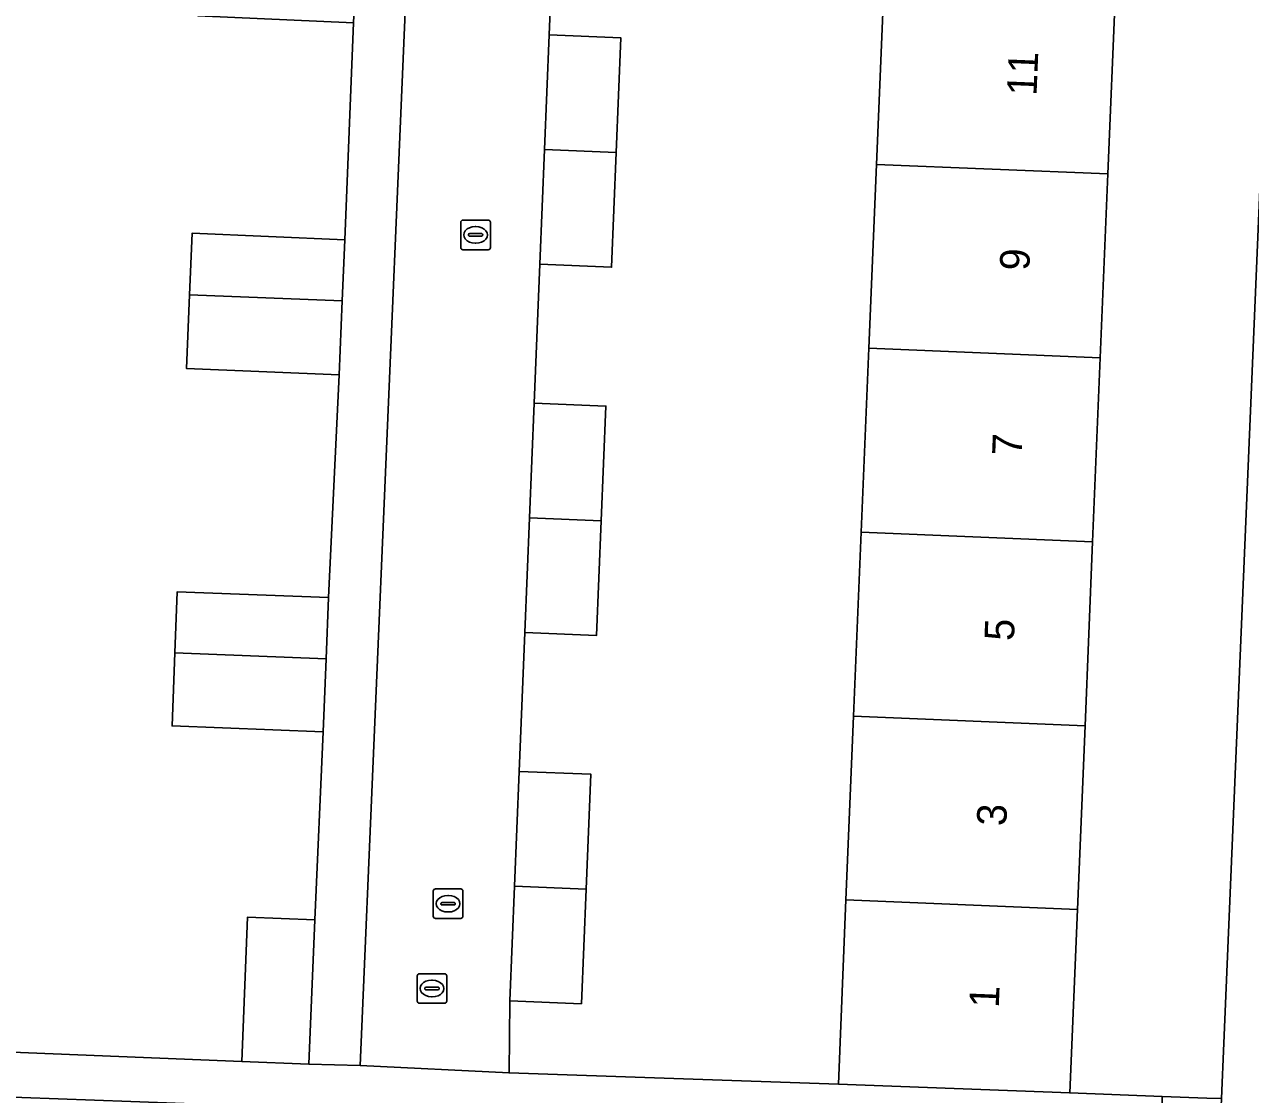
# Model space of a CAD drawing. Extents: x 161354 to 162026, y 386504 to 387460.
# Drawn here: x 161513.06 to 161554.51, y 386686.96 to 386723.13 of the extents above; entities that cross this region are included whole.
import ezdxf

# ---------------------------------------------------------------- set-up
doc = ezdxf.new("R2010")
doc.units = 0
for name, color, linetype in [('IMGEO_Erf', 7, 'Continuous'), ('IMGEO_Kolk', 7, 'Continuous'), ('IMGEO_Pand', 7, 'Continuous'), ('IMGEO_Pand_nummerreeks', 7, 'Continuous'), ('IMGEO_Rijbaan_lokaal_open', 7, 'Continuous'), ('IMGEO_Rioolput', 7, 'Continuous'), ('IMGEO_Voetpad_open', 7, 'Continuous')]:
    doc.layers.add(name, color=color, linetype=linetype)

msp = doc.modelspace()

# ---------------------------------------------------------------- linework, layer by layer
at = {"layer": 'IMGEO_Erf'}
for points in [[(161549.945, 386724.294), (161549.688, 386718.078), (161549.43, 386711.861), (161549.173, 386705.644), (161548.916, 386699.427), (161548.658, 386693.211), (161548.402, 386687.013), (161551.52, 386686.895), (161553.035, 386686.838), (161553.534, 386686.819), (161556.007, 386745.625)], [(161496.538, 386689.04), (161520.399, 386688.074), (161520.597, 386692.953), (161522.87, 386692.861), (161523.157, 386699.22), (161518.043, 386699.418), (161518.138, 386701.89), (161518.218, 386703.953), (161523.332, 386703.755), (161523.69, 386711.288), (161518.532, 386711.505), (161518.637, 386713.996), (161518.724, 386716.073), (161523.882, 386715.856), (161524.182, 386723.194), (161518.919, 386723.421), (161519.035, 386726.105), (161519.121, 386728.084), (161524.383, 386727.857), (161524.785, 386736.896), (161522.407, 386736.993), (161522.622, 386742.251), (161521.337, 386742.294), (161500, 386743.01)], [(161530.986, 386727.476), (161530.794, 386722.78), (161533.222, 386722.68), (161533.064, 386718.803), (161532.906, 386714.926), (161530.478, 386715.026), (161530.286, 386710.332), (161532.714, 386710.231), (161532.556, 386706.354), (161532.398, 386702.477), (161529.97, 386702.578), (161529.778, 386697.882), (161532.206, 386697.782), (161532.048, 386693.905), (161531.889, 386690.028), (161529.461, 386690.128), (161529.439, 386687.685), (161540.576, 386687.31), (161540.833, 386693.535), (161541.091, 386699.751), (161541.348, 386705.968), (161541.605, 386712.185), (161541.863, 386718.402), (161542.12, 386724.618)]]:
    msp.add_lwpolyline(points, dxfattribs=at)
at = {"layer": 'IMGEO_Kolk'}
for p, q in [((161527.807, 386715.593), (161527.807, 386716.445)), ((161527.882, 386716.519), (161528.734, 386716.519)), ((161528.295, 386716.299), (161528.32, 386716.299)), ((161528.808, 386716.445), (161528.808, 386715.593)), ((161528.066, 386716.013), (161528.066, 386716.025)), ((161528.504, 386715.976), (161528.106, 386715.976)), ((161528.109, 386716.062), (161528.507, 386716.062)), ((161528.318, 386715.739), (161528.293, 386715.739)), ((161528.55, 386716.025), (161528.55, 386716.013)), ((161528.734, 386715.519), (161527.882, 386715.519)), ((161526.879, 386692.982), (161526.879, 386693.834)), ((161526.954, 386693.908), (161527.806, 386693.908)), ((161527.88, 386693.834), (161527.88, 386692.982)), ((161527.138, 386693.402), (161527.138, 386693.414)), ((161527.576, 386693.365), (161527.178, 386693.365)), ((161527.181, 386693.451), (161527.579, 386693.451)), ((161527.367, 386693.688), (161527.392, 386693.688)), ((161527.622, 386693.414), (161527.622, 386693.402)), ((161527.806, 386692.908), (161526.954, 386692.908)), ((161527.39, 386693.128), (161527.365, 386693.128))]:
    msp.add_line(p, q, dxfattribs=at)
for points in [[(161527.807, 386715.593), (161527.807, 386716.445)], [(161527.882, 386716.519), (161528.734, 386716.519)], [(161528.808, 386716.445), (161528.808, 386715.593)], [(161528.734, 386715.519), (161527.882, 386715.519)], [(161526.879, 386692.982), (161526.879, 386693.834)], [(161526.954, 386693.908), (161527.806, 386693.908)], [(161527.88, 386693.834), (161527.88, 386692.982)], [(161527.806, 386692.908), (161526.954, 386692.908)]]:
    msp.add_lwpolyline(points, dxfattribs=at)
for centre, radius, start, end in [((161527.884, 386716.443), 0.0765, 91.552, 178.448), ((161527.884, 386716.443), 0.0765, 91.552, 178.448), ((161528.732, 386716.443), 0.0765, 1.552, 88.448), ((161528.732, 386716.443), 0.0765, 1.552, 88.448), ((161528.106, 386716.022), 0.0403, 85.8775, 175.7526), ((161528.103, 386716.012), 0.0366, 178.938, 274.7102), ((161528.507, 386716.019), 0.043, 264.8664, 352.4533), ((161528.511, 386716.024), 0.0386, 1.7309, 96.639), ((161527.884, 386715.595), 0.0765, 181.552, 268.448), ((161527.884, 386715.595), 0.0765, 181.552, 268.448), ((161528.732, 386715.595), 0.0765, 271.552, 358.448), ((161528.732, 386715.595), 0.0765, 271.552, 358.448), ((161526.956, 386693.832), 0.0765, 91.552, 178.448), ((161526.956, 386693.832), 0.0765, 91.552, 178.448), ((161527.804, 386693.832), 0.0765, 1.552, 88.448), ((161527.804, 386693.832), 0.0765, 1.552, 88.448), ((161527.178, 386693.411), 0.0403, 85.8775, 175.7526), ((161527.175, 386693.401), 0.0366, 178.938, 274.7102), ((161527.579, 386693.408), 0.043, 264.8664, 352.4533), ((161527.583, 386693.413), 0.0386, 1.7309, 96.639), ((161526.956, 386692.984), 0.0765, 181.552, 268.448), ((161526.956, 386692.984), 0.0765, 181.552, 268.448), ((161527.804, 386692.984), 0.0765, 271.552, 358.448), ((161527.804, 386692.984), 0.0765, 271.552, 358.448)]:
    msp.add_arc(centre, radius, start, end, dxfattribs=at)
for centre, major_axis, ratio, start_param, end_param in [((161528.294, 386716.019), (-0.387, 0.002), 0.722429, 4.712389, 7.853982), ((161528.319, 386716.019), (-0.39, 0.002), 0.717154, 1.570796, 4.712389), ((161527.366, 386693.408), (-0.387, 0.002), 0.722429, 4.712389, 7.853982), ((161527.391, 386693.408), (-0.39, 0.002), 0.717154, 1.570796, 4.712389)]:
    msp.add_ellipse(centre, major_axis=major_axis, ratio=ratio, start_param=start_param, end_param=end_param, dxfattribs=at)
at = {"layer": 'IMGEO_Pand'}
for points in [[(161549.688, 386718.078), (161549.945, 386724.294), (161542.12, 386724.618), (161541.863, 386718.402)], [(161533.222, 386722.68), (161530.794, 386722.78), (161530.636, 386718.903), (161533.064, 386718.803)], [(161533.064, 386718.803), (161530.636, 386718.903), (161530.478, 386715.026), (161532.906, 386714.926)], [(161549.43, 386711.861), (161549.688, 386718.078), (161541.863, 386718.402), (161541.605, 386712.185)], [(161523.882, 386715.856), (161518.724, 386716.073), (161518.637, 386713.996), (161523.795, 386713.795)], [(161523.795, 386713.795), (161518.637, 386713.996), (161518.532, 386711.505), (161523.69, 386711.288)], [(161541.605, 386712.185), (161541.348, 386705.968), (161549.173, 386705.644), (161549.43, 386711.861)], [(161532.714, 386710.231), (161530.286, 386710.332), (161530.128, 386706.455), (161532.556, 386706.354)], [(161532.556, 386706.354), (161530.128, 386706.455), (161529.97, 386702.578), (161532.398, 386702.477)], [(161541.348, 386705.968), (161541.091, 386699.751), (161548.916, 386699.427), (161549.173, 386705.644)], [(161523.332, 386703.755), (161518.218, 386703.953), (161518.138, 386701.89), (161523.252, 386701.692)], [(161523.252, 386701.692), (161518.138, 386701.89), (161518.043, 386699.418), (161523.157, 386699.22)], [(161548.658, 386693.211), (161548.916, 386699.427), (161541.091, 386699.751), (161540.833, 386693.535)], [(161532.206, 386697.782), (161529.778, 386697.882), (161529.619, 386694.005), (161532.048, 386693.905)], [(161532.048, 386693.905), (161529.619, 386694.005), (161529.461, 386690.128), (161531.889, 386690.028)], [(161548.658, 386693.211), (161540.833, 386693.535), (161540.576, 386687.31), (161548.402, 386687.013)], [(161522.87, 386692.861), (161520.597, 386692.953), (161520.399, 386688.074), (161522.672, 386687.982)]]:
    msp.add_lwpolyline(points, close=True, dxfattribs=at)
at = {"layer": 'IMGEO_Rijbaan_lokaal_open'}
msp.add_lwpolyline([(161556.221, 386751.504), (161556.166, 386750), (161556.007, 386745.625), (161553.534, 386686.819), (161552.686, 386666.678), (161552.424, 386660.44)], dxfattribs=at)
msp.add_lwpolyline([(161530.636, 386718.903), (161530.794, 386722.78), (161530.986, 386727.476), (161531.144, 386731.353), (161531.302, 386735.23), (161531.398, 386737.577), (161531.657, 386743.931), (161531.769, 386746.655), (161530.64, 386746.711), (161530.713, 386748.117), (161526.871, 386748.302), (161526.786, 386744.962), (161526.711, 386742.045), (161524.41, 386687.933), (161529.439, 386687.685), (161529.461, 386690.128), (161529.619, 386694.005), (161529.778, 386697.882), (161529.97, 386702.578), (161530.128, 386706.455), (161530.286, 386710.332), (161530.478, 386715.026)], close=True, dxfattribs=at)
at = {"layer": 'IMGEO_Rioolput'}
for p, q in [((161526.334, 386690.115), (161526.334, 386690.967)), ((161526.409, 386691.041), (161527.261, 386691.041)), ((161526.822, 386690.821), (161526.847, 386690.821)), ((161527.335, 386690.967), (161527.335, 386690.115)), ((161526.593, 386690.535), (161526.593, 386690.547)), ((161527.031, 386690.498), (161526.633, 386690.498)), ((161526.636, 386690.584), (161527.034, 386690.584)), ((161527.077, 386690.547), (161527.077, 386690.535)), ((161527.261, 386690.041), (161526.409, 386690.041)), ((161526.845, 386690.261), (161526.82, 386690.261))]:
    msp.add_line(p, q, dxfattribs=at)
for points in [[(161526.334, 386690.115), (161526.334, 386690.967)], [(161526.409, 386691.041), (161527.261, 386691.041)], [(161527.335, 386690.967), (161527.335, 386690.115)], [(161527.261, 386690.041), (161526.409, 386690.041)]]:
    msp.add_lwpolyline(points, dxfattribs=at)
for centre, radius, start, end in [((161526.411, 386690.965), 0.0765, 91.552, 178.448), ((161526.411, 386690.965), 0.0765, 91.552, 178.448), ((161527.259, 386690.965), 0.0765, 1.552, 88.448), ((161527.259, 386690.965), 0.0765, 1.552, 88.448), ((161526.633, 386690.544), 0.0403, 85.8775, 175.7526), ((161526.63, 386690.534), 0.0366, 178.938, 274.7102), ((161527.034, 386690.541), 0.043, 264.8664, 352.4533), ((161527.038, 386690.546), 0.0386, 1.7309, 96.639), ((161526.411, 386690.117), 0.0765, 181.552, 268.448), ((161526.411, 386690.117), 0.0765, 181.552, 268.448), ((161527.259, 386690.117), 0.0765, 271.552, 358.448), ((161527.259, 386690.117), 0.0765, 271.552, 358.448)]:
    msp.add_arc(centre, radius, start, end, dxfattribs=at)
for centre, major_axis, ratio, start_param, end_param in [((161526.821, 386690.541), (-0.387, 0.002), 0.722429, 4.712389, 7.853982), ((161526.846, 386690.541), (-0.39, 0.002), 0.717154, 1.570796, 4.712389)]:
    msp.add_ellipse(centre, major_axis=major_axis, ratio=ratio, start_param=start_param, end_param=end_param, dxfattribs=at)
at = {"layer": 'IMGEO_Voetpad_open'}
msp.add_lwpolyline([(161524.299, 386725.901), (161524.182, 386723.194), (161523.882, 386715.856), (161523.795, 386713.795), (161523.69, 386711.288), (161523.332, 386703.755), (161523.252, 386701.692), (161523.157, 386699.22), (161522.87, 386692.861), (161522.672, 386687.982), (161524.41, 386687.933), (161526.711, 386742.045), (161525, 386742.154), (161524.785, 386736.896), (161524.383, 386727.857)], close=True, dxfattribs=at)
msp.add_lwpolyline([(161511.72, 386686.904), (161516.655, 386686.717), (161520.56, 386686.569), (161524.435, 386686.422), (161529.128, 386686.243), (161532.999, 386686.097), (161536.876, 386685.949), (161541.59, 386685.783), (161545.467, 386685.624), (161551.489, 386685.395), (161551.52, 386686.895), (161548.402, 386687.013), (161540.576, 386687.31), (161529.439, 386687.685), (161524.41, 386687.933), (161522.672, 386687.982), (161520.399, 386688.074), (161496.538, 386689.04)], dxfattribs=at)

# ---------------------------------------------------------------- texts
at = {"layer": 'IMGEO_Pand_nummerreeks'}
for s, rotation, p in [('11', 87.6294, (161547.275, 386720.711)), ('9', 87.6294, (161547.029, 386714.798)), ('7', 87.6294, (161546.77, 386708.539)), ('5', 87.6294, (161546.511, 386702.28)), ('3', 87.6294, (161546.252, 386696.021)), ('1', 87.6282, (161545.998, 386689.875))]:
    msp.add_text(s, height=1, rotation=rotation, dxfattribs=at).set_placement(p)

doc.saveas('drawing.dxf')
